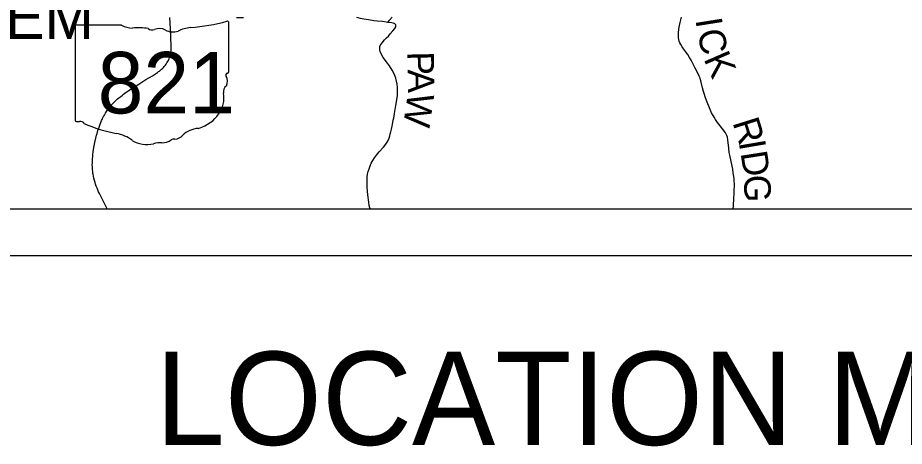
# Model space of a CAD drawing. Extents: x 0 to 34, y 0 to 22.
# Drawn here: x 4.132 to 6.032, y 13.591 to 14.51 of the extents above; entities that cross this region are included whole.
import ezdxf

# ---------------------------------------------------------------- set-up
doc = ezdxf.new("R2010")
doc.units = 0
for name, color, linetype in [('GM_X_Corporation', 7, 'Continuous'), ('GM_X_Corporation_Text', 7, 'Continuous'), ('GM_X_State_Location', 7, 'Continuous'), ('GM_X_State_Route', 7, 'Continuous'), ('GM_X_State_Shield', 7, 'Continuous'), ('GM_X_Township_Road', 7, 'Continuous'), ('GM_X_Township_Road_Text', 7, 'Continuous'), ('SH_Data', 7, 'Continuous'), ('SH_Text', 7, 'Continuous')]:
    doc.layers.add(name, color=color, linetype=linetype)

msp = doc.modelspace()

# ---------------------------------------------------------------- linework, layer by layer
at = {"layer": 'GM_X_Corporation'}
msp.add_lwpolyline([(2.1, 19.4241), (2.1, 14.1), (8.9, 14.1), (8.9, 16.8499)], dxfattribs=at)
at = {"layer": 'GM_X_State_Route'}
for points in [[(4.4598, 14.4355), (4.4602, 14.4398), (4.4603, 14.443), (4.4604, 14.4459), (4.4604, 14.4484), (4.4603, 14.4509), (4.4602, 14.4539), (4.4601, 14.457), (4.46, 14.4607), (4.46, 14.4631), (4.4597, 14.4685), (4.4596, 14.4715), (4.4594, 14.4752), (4.4574, 14.5103)], [(4.3235, 14.1), (4.3156, 14.1155), (4.3088, 14.1287), (4.3068, 14.1327), (4.305, 14.1366), (4.3031, 14.1408), (4.3016, 14.1446), (4.2999, 14.1489), (4.2985, 14.1529), (4.2973, 14.1569), (4.296, 14.1611), (4.2948, 14.1661), (4.2939, 14.1703), (4.2932, 14.1742), (4.2928, 14.1765), (4.2925, 14.1787), (4.2922, 14.181), (4.2919, 14.1837), (4.2916, 14.187), (4.2915, 14.1902), (4.2914, 14.1943), (4.2915, 14.1986), (4.2918, 14.2071), (4.2923, 14.2122), (4.2928, 14.2169), (4.2935, 14.2222), (4.2943, 14.2274), (4.2957, 14.2352), (4.2971, 14.242), (4.2992, 14.2517), (4.3006, 14.2578), (4.3017, 14.262), (4.3035, 14.2683), (4.3051, 14.2733), (4.3066, 14.2775), (4.308, 14.2815), (4.3096, 14.2855), (4.3113, 14.2896), (4.3124, 14.292), (4.3134, 14.2941), (4.3154, 14.2978), (4.3173, 14.3013), (4.3197, 14.3053), (4.3218, 14.3087), (4.3235, 14.3112), (4.3254, 14.3139), (4.3277, 14.3171), (4.3303, 14.3203), (4.332, 14.3222), (4.3336, 14.324), (4.3362, 14.3267), (4.3395, 14.33), (4.3425, 14.3328), (4.3456, 14.3357), (4.3485, 14.3382), (4.3523, 14.3413), (4.3558, 14.3441), (4.3583, 14.346), (4.361, 14.348), (4.3685, 14.353), (4.3737, 14.3565), (4.3909, 14.3676), (4.4061, 14.3772), (4.4202, 14.3856), (4.4226, 14.3871), (4.4247, 14.3884), (4.4268, 14.3898), (4.4287, 14.3911), (4.4311, 14.3926), (4.4335, 14.3943), (4.4354, 14.3956), (4.4367, 14.3965), (4.4378, 14.3975), (4.4399, 14.3993), (4.4422, 14.4014), (4.444, 14.4032), (4.4458, 14.4053), (4.4481, 14.4082), (4.4496, 14.4104), (4.4513, 14.4129), (4.4529, 14.4155), (4.4544, 14.4181), (4.4554, 14.42), (4.4562, 14.4218), (4.4572, 14.4244), (4.4578, 14.4266), (4.4584, 14.4285), (4.4588, 14.4302), (4.4593, 14.4325), (4.4598, 14.4355)]]:
    msp.add_lwpolyline(points, dxfattribs=at)
at = {"layer": 'GM_X_State_Shield'}
for p, q in [((4.2543, 14.4907), (4.2543, 14.2906)), ((4.3541, 14.4942), (4.2576, 14.4942)), ((4.5839, 14.3944), (4.5839, 14.4991)), ((4.5839, 14.3945), (4.5839, 14.3944))]:
    msp.add_line(p, q, dxfattribs=at)
for centre, major_axis, start_param, end_param in [((4.4665, 14.767), (0.3495, 0), 4.814394, 5.042369), ((4.5803, 14.4995), (0.00367, 0), 6.141152, 7.989035), ((4.2581, 14.4911), (0.00382, 0), 1.712693, 3.28349), ((4.3771, 14.5174), (0.037, 0), 4.042523, 4.731795), ((4.3894, 14.3818), (0.133, 0), 1.404758, 1.657858), ((4.4196, 14.4922), (0.0107, 0), 3.836095, 5.185415), ((4.4352, 14.469), (0.0222, 0), 0.950623, 2.079405), ((4.4639, 14.5008), (0.0267, 0), 4.081561, 5.145723), ((4.5111, 14.433), (0.0703, 0), 1.699011, 2.107814), ((4.5831, 14.3867), (0.00568, 0), 1.883978, 3.671073), ((4.58, 14.394), (0.00393, 0), 5.05454, 6.418171), ((4.547, 14.3735), (0.0341, 0), 5.934695, 6.695948), ((4.5971, 14.3506), (0.0248, 0), 2.387724, 3.262537), ((4.4861, 14.3373), (0.0874, 0), 5.101752, 6.440018), ((4.2582, 14.2901), (0.00385, 0), 3.00124, 4.508301), ((4.2587, 14.3106), (0.0294, 0), 4.665946, 4.897461), ((4.2648, 14.279), (0.0106, 0), 0.519207, 1.627899), ((4.3986, 14.4588), (0.2524, 0), 4.195997, 4.488961), ((4.3233, 14.2007), (0.079, 0), 0.823519, 1.323587), ((4.4623, 14.2712), (0.0282, 0), 4.937069, 5.64225), ((4.523, 14.2344), (0.0479, 0), 1.647645, 2.488434), ((4.4087, 14.278), (0.0501, 0), 4.026481, 4.996735), ((4.4377, 14.2089), (0.0412, 0), 1.495662, 1.94098), ((4.4414, 14.2631), (0.0267, 0), 4.691044, 5.507374), ((4.4655, 14.2437), (0.00752, 0), 1.147584, 2.315152)]:
    msp.add_ellipse(centre, major_axis=major_axis, ratio=0.8, start_param=start_param, end_param=end_param, dxfattribs=at)
at = {"layer": 'GM_X_Township_Road'}
for points in [[(4.6158, 14.51), (4.6114, 14.5096), (4.6065, 14.5095), (4.6003, 14.51)], [(4.9248, 14.5), (4.9217, 14.5004), (4.9137, 14.5015), (4.902, 14.5028), (4.8946, 14.5036), (4.8835, 14.5051), (4.8737, 14.5068), (4.8664, 14.5083), (4.8586, 14.5102)], [(4.9248, 14.5), (4.9284, 14.5045), (4.9339, 14.5112)], [(5.6429, 14.2707), (5.6423, 14.2715), (5.6373, 14.2778), (5.6318, 14.2852), (5.6272, 14.2917), (5.6243, 14.2964), (5.6221, 14.3001), (5.6191, 14.3062), (5.6142, 14.3169), (5.6092, 14.329), (5.6058, 14.3383), (5.6029, 14.3471), (5.6015, 14.3518), (5.5995, 14.3596), (5.5968, 14.3716), (5.5953, 14.377), (5.5942, 14.3805), (5.5926, 14.3845), (5.5887, 14.3922), (5.5839, 14.4017), (5.5798, 14.41), (5.5753, 14.4189), (5.572, 14.4249), (5.5679, 14.4311), (5.5612, 14.4401), (5.5558, 14.4476), (5.5528, 14.4523), (5.5508, 14.4562), (5.5496, 14.4597), (5.5487, 14.4633), (5.5483, 14.4669), (5.5483, 14.4712), (5.5482, 14.4772), (5.5491, 14.4851), (5.5505, 14.4931), (5.5518, 14.4995), (5.5532, 14.5056), (5.5542, 14.5109)], [(4.887, 14.1), (4.8863, 14.1021), (4.8851, 14.1075), (4.8841, 14.1142), (4.8823, 14.1303), (4.8817, 14.1377), (4.8809, 14.1469), (4.8807, 14.1506), (4.8805, 14.1556), (4.8805, 14.1612), (4.8809, 14.168), (4.8816, 14.1742), (4.8829, 14.1803), (4.8846, 14.1862), (4.8868, 14.192), (4.8894, 14.1977), (4.8927, 14.2036), (4.8964, 14.2094), (4.9005, 14.2149), (4.9065, 14.222), (4.9153, 14.2324), (4.9204, 14.2387), (4.9235, 14.2434), (4.9256, 14.2469), (4.9277, 14.2517), (4.9292, 14.2564), (4.9303, 14.2612), (4.9311, 14.2649), (4.9326, 14.2709), (4.934, 14.2775), (4.9349, 14.2818), (4.9357, 14.2854), (4.9367, 14.2903), (4.9375, 14.2945), (4.939, 14.3042), (4.9405, 14.3131), (4.9423, 14.322), (4.9445, 14.3337), (4.9455, 14.3432), (4.9458, 14.3526), (4.9456, 14.3602), (4.945, 14.3675), (4.9438, 14.3739), (4.9423, 14.38), (4.9385, 14.3895), (4.9343, 14.3977), (4.9283, 14.4066), (4.9219, 14.4152), (4.915, 14.4248), (4.9112, 14.4314), (4.9085, 14.4377), (4.9079, 14.4408), (4.9077, 14.4448), (4.908, 14.4479), (4.9088, 14.4503), (4.9108, 14.4534), (4.913, 14.4563), (4.9181, 14.4623), (4.9223, 14.4667), (4.9261, 14.4707), (4.9301, 14.4752), (4.9359, 14.4818), (4.9396, 14.4867), (4.9418, 14.4907), (4.9422, 14.4935), (4.9419, 14.4947), (4.9412, 14.4957), (4.9399, 14.497), (4.9388, 14.4976), (4.9365, 14.4984), (4.9334, 14.4989), (4.9248, 14.5)], [(5.6652, 14.1), (5.6653, 14.1018), (5.6657, 14.1048), (5.6658, 14.1078), (5.6661, 14.1121), (5.6665, 14.117), (5.6669, 14.1245), (5.6675, 14.1318), (5.6677, 14.1368), (5.6678, 14.1535), (5.6677, 14.1591), (5.6673, 14.1641), (5.6667, 14.1696), (5.6656, 14.1776), (5.6642, 14.1849), (5.6607, 14.2014), (5.6579, 14.2154), (5.657, 14.2209), (5.6557, 14.2301), (5.6539, 14.248), (5.6528, 14.2535), (5.6514, 14.2576), (5.6496, 14.2615), (5.6486, 14.2631), (5.6469, 14.2657), (5.6429, 14.2707)]]:
    msp.add_lwpolyline(points, dxfattribs=at)
at = {"layer": 'SH_Data'}
for p, q in [((2.1, 14.1), (8.9, 14.1)), ((2, 14), (9, 14))]:
    msp.add_line(p, q, dxfattribs=at)
at = {"layer": 'SH_Text'}
msp.add_lwpolyline([(2.1, 16.074), (2.1, 14.1), (6.4323, 14.1)], dxfattribs=at)

# ---------------------------------------------------------------- texts
at = {"layer": 'GM_X_Corporation_Text'}
msp.add_text('LOWER SALEM', height=0.094697, rotation=0, dxfattribs=at).set_placement((3.3656, 14.4642))
at = {"layer": 'GM_X_State_Location'}
for s in ['s', 'r']:
    msp.add_text(s, height=0.000189, dxfattribs=at).set_placement((4.4154, 14.3773))
msp.add_text('821', height=0.000189, rotation=0, dxfattribs=at).set_placement((4.3486, 14.3636))
at = {"layer": 'GM_X_State_Shield'}
msp.add_text('821', height=0.13184, dxfattribs=at).set_placement((4.3029, 14.3047))
at = {"layer": 'GM_X_Township_Road_Text'}
for s, rotation, p in [('I', 279.0725, (5.5841, 14.5058)), ('C', 281.3138, (5.5882, 14.4804)), ('P', 271.131, (4.9668, 14.4371)), ('K', 293.5754, (5.6013, 14.422)), ('A', 270.5756, (4.9675, 14.3989)), ('W', 261.7854, (4.9682, 14.3512)), ('R', 287.4043, (5.6635, 14.2854)), ('I', 279.6946, (5.677, 14.2429)), ('D', 278.9024, (5.6809, 14.2201)), ('G', 271.2059, (5.6884, 14.1727))]:
    msp.add_text(s, height=0.0568, rotation=rotation, dxfattribs=at).set_placement(p)
at = {"layer": 'SH_Text'}
msp.add_text('LOCATION MAP', height=0.2, dxfattribs=at).set_placement((4.4269, 13.5937))

doc.saveas('drawing.dxf')
